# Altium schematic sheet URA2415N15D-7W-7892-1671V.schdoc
size 277 x 190 mm; Device: default297x210; Symbol: default297x210; Name: default297x210; Date: 2026.04.20; Rev: V1.1; Size: "A4"; Id: /; File: URA2415N15D-7W-7892-1671V; Sheet: /
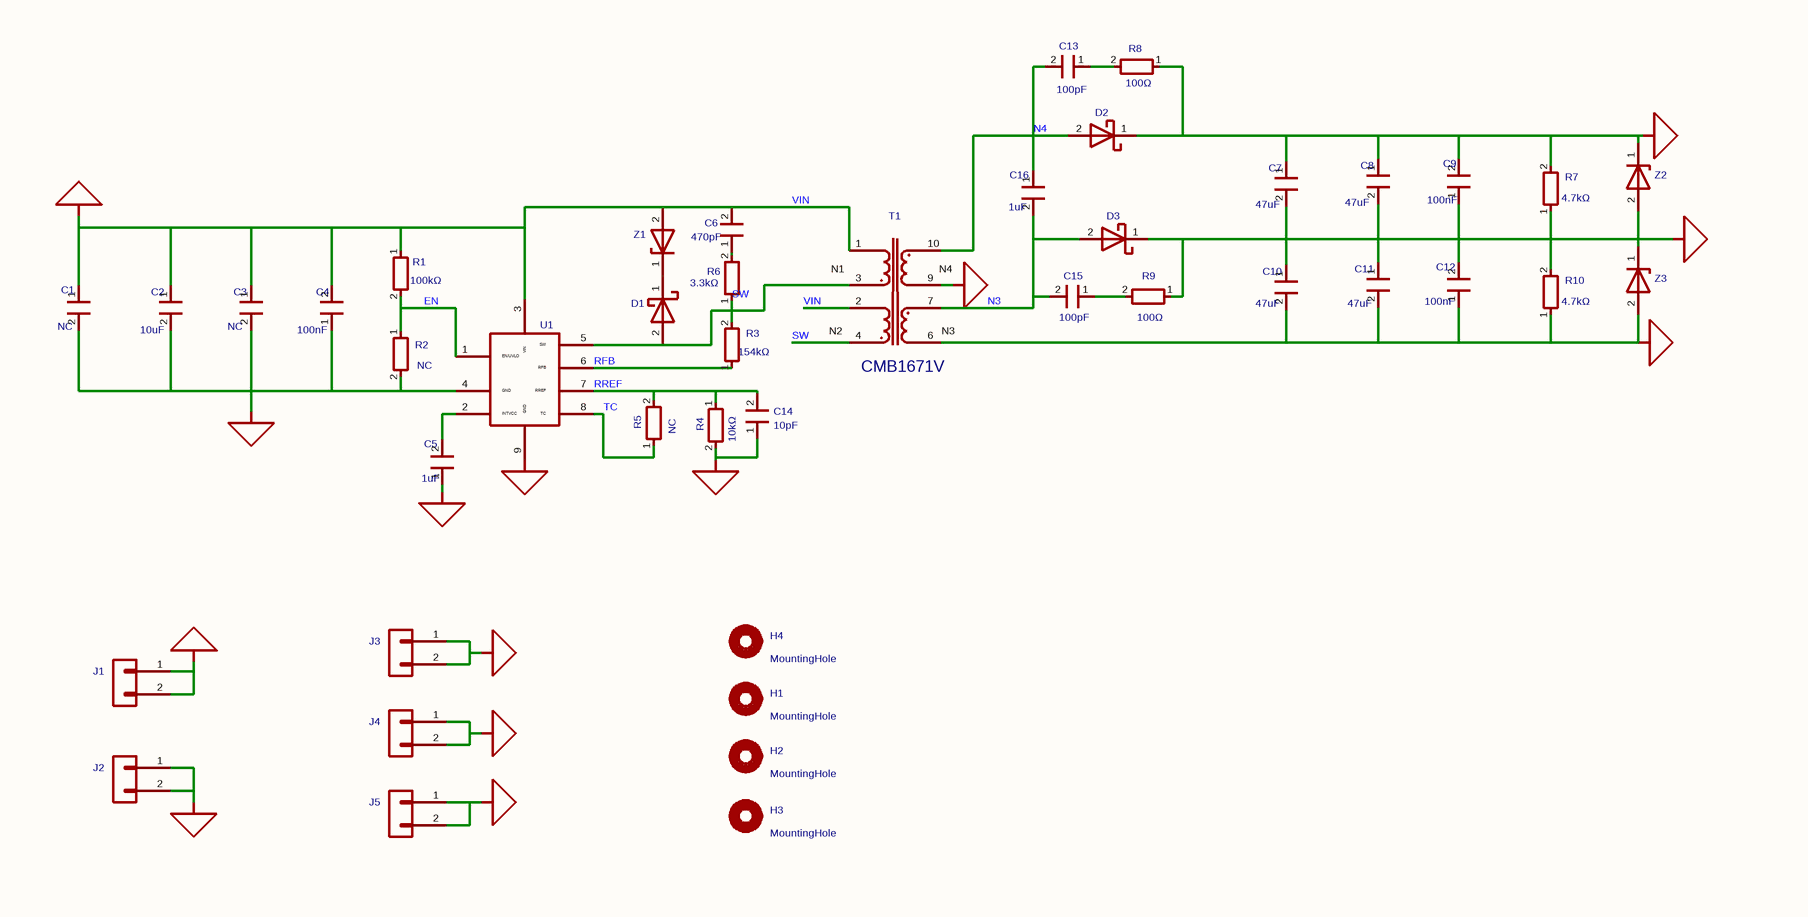
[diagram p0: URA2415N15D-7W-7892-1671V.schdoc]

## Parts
C1  value NC  [MYLibrary:C1206]  (hidden comment: MY_C)
C2  10uF  [MYLibrary:C1206]
C3  value NC  [MYLibrary:C0805]  (hidden comment: MY_C)
C4  100nF  [MYLibrary:C0603]
C5  1uF  [MYLibrary:C0603]
C6  470pF  [MYLibrary:C0603]
C7  47uF  [MYLibrary:C1206]
C8  47uF  [MYLibrary:C1206]
C9  100nF  [MYLibrary:C0603]
C10  47uF  [MYLibrary:C1206]
C11  47uF  [MYLibrary:C1206]
C12  100nF  [MYLibrary:C0603]
C13  100pF  [MYLibrary:C0603]
C14  10pF  [MYLibrary:C0603]
C15  100pF  [MYLibrary:C0603]
C16  1uF  [MYLibrary:C0805]
D1  DSS210  [Diode_SMD:D_SOD-123]  (value not drawn)
D2  SS210F  [Diode_SMD:D_SMA_Handsoldering]  (value not drawn)
D3  SS210F  [Diode_SMD:D_SMA_Handsoldering]  (value not drawn)
H1  value MountingHole  [MountingHole:MountingHole_3.2mm_M3_DIN965]  (hidden comment: Mechanical_MountingHole)
H2  value MountingHole  [MountingHole:MountingHole_3.2mm_M3_DIN965]  (hidden comment: Mechanical_MountingHole)
H3  value MountingHole  [MountingHole:MountingHole_3.2mm_M3_DIN965]  (hidden comment: Mechanical_MountingHole)
H4  value MountingHole  [MountingHole:MountingHole_3.2mm_M3_DIN965]  (hidden comment: Mechanical_MountingHole)
J1  HX PZ2.54-1x2P ZZ  [Connector_PinHeader_2.54mm:PinHeader_1x02_P2.54mm_Vertical]  (value not drawn)
J2  HX PZ2.54-1x2P ZZ  [Connector_PinHeader_2.54mm:PinHeader_1x02_P2.54mm_Vertical]  (value not drawn)
J3  HX PZ2.54-1x2P ZZ  [Connector_PinHeader_2.54mm:PinHeader_1x02_P2.54mm_Vertical]  (value not drawn)
J4  HX PZ2.54-1x2P ZZ  [Connector_PinHeader_2.54mm:PinHeader_1x02_P2.54mm_Vertical]  (value not drawn)
J5  HX PZ2.54-1x2P ZZ  [Connector_PinHeader_2.54mm:PinHeader_1x02_P2.54mm_Vertical]  (value not drawn)
R1  100kΩ  [MYLibrary:R0603]
R2  value NC  [MYLibrary:R0603]  (hidden comment: Device_R_Small)
R3  154kΩ  [MYLibrary:R0603]
R4  10kΩ  [MYLibrary:R0603]
R5  value NC  [MYLibrary:R0603]  (hidden comment: Device_R_Small)
R6  3.3kΩ  [MYLibrary:R1206]
R7  4.7kΩ  [MYLibrary:R1206]
R8  100Ω  [MYLibrary:R0603]
R9  100Ω  [MYLibrary:R0603]
R10  4.7kΩ  [MYLibrary:R1206]
T1  CMB1671V  [MYLibrary:EP13_9PIN]
U1  CMP7892  [Package_SO:SOIC-8-1EP_3.9x4.9mm_P1.27mm_EP2.41x3.3mm_ThermalVias]  (value not drawn)
Z1  1SMA4747A  [Diode_SMD:D_SMA]  (value not drawn)
Z2  Diode_BZV55C75  [Diode_SMD:D_SMA]  (value not drawn)
Z3  Diode_BZV55C75  [Diode_SMD:D_SMA]  (value not drawn)

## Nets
-VOUT2: C10.2 C11.2 C12.1 J5.1(Pin_1) J5.2(Pin_2) R10.1 T1.6 Z3.2(A)
GND1: C1.2 C2.2 C3.2 C4.1 C5.1 C14.1 J2.1(Pin_1) J2.2(Pin_2) R2.2 R4.2 U1.4(GND) U1.9(GND)
GND2: C7.2 C8.2 C9.1 C10.1 C11.1 C12.2 D3.1(K) J4.1(Pin_1) J4.2(Pin_2) R7.1 R9.1 R10.2 T1.9 Z2.2(A) Z3.1(K)
VIN: C1.1 C2.1 C3.1 C4.2 C6.2 J1.1(Pin_1) J1.2(Pin_2) R1.1 T1.1 T1.2 U1.3(VIN) Z1.2(A)
VOUT1: C7.1 C8.1 C9.2 D2.1(K) J3.1(Pin_1) J3.2(Pin_2) R7.2 R8.1 Z2.1(K)
EN: R1.2 R2.1 U1.1(EN/UVLO)
N3: C15.2 C16.2 D3.2(A) T1.7
N4: C13.2 C16.1 D2.2(A) T1.10
RFB: R3.1 U1.6(RFB)
RREF: C14.2 R4.1 R5.2 U1.7(RREF)
SW: D1.2(A) R3.2 R6.1 T1.3 T1.4 U1.5(SW)
TC: R5.1 U1.8(TC)
NetC5_2: C5.2 U1.2(INTVCC)
NetC6_1: C6.1 R6.2
NetC13_1: C13.1 R8.2
NetC15_1: C15.1 R9.2
NetD1_1: D1.1(K) Z1.1(K)

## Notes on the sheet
- (near T1) N2
- (near T1) N1
- (near T1) N4
- (near T1) N3

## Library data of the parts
C1 = MY_C: Add into BOM: no; ki_keywords: cap capacitor; ki_fp_filters: C_*; Attribute1: C11
C2 = CC1206KKX5R9BB106: 容值:10uF;精度:±10%;额定电压:50V;温度系数:X5R;; Manufacturer: YAGEO(国巨); Symbol: MY_C; Add into BOM: yes; 3D Model: e4be705b945545a48e666415e3682bd8; 3D Model Transform: 125.984,62.992,0,0,0,0,0,0,0; Tolerance: ±10%; Voltage Rating: 50V; Temperature Coefficient: X5R; ki_keywords: cap capacitor; ki_fp_filters: C_*; ModelName: C1206_L3.2-W1.6-H1.3
C3 = MY_C: 0805; Add into BOM: no; ki_keywords: cap capacitor; ki_fp_filters: C_*; Attribute1: C16
C4 C9 C12 = CC0603KRX7R9BB104: 容值:100nF;精度:±10%;额定电压:50V;温度系数:X7R;; Manufacturer: YAGEO(国巨); Symbol: MY_C; Add into BOM: yes; 3D Model: ac125912035d415993ca9572d50418b1; 3D Model Transform: 62.992,31.496,0,0,0,0,0,0,0; Tolerance: ±10%; Voltage Rating: 50V; Temperature Coefficient: X7R; ki_keywords: cap capacitor; ki_fp_filters: C_*; ModelName: C0603_L1.6-W0.8-H0.8
C5 = CC0603KRX7R9BB105: 容值:1uF;精度:±10%;额定电压:50V;温度系数:X7R;; Manufacturer: YAGEO(国巨); Symbol: MY_C; Add into BOM: yes; 3D Model: ac125912035d415993ca9572d50418b1; 3D Model Transform: 62.992,31.496,0,0,0,0,0,0,0; Tolerance: ±10%; Voltage Rating: 50V; Temperature Coefficient: X7R; ki_keywords: cap capacitor; ki_fp_filters: C_*; UniqueId: 05d417a4d81547fc; ModelName: C0603_L1.6-W0.8-H0.8
C6 = CC0603KRX7R9BB471: 容值:470pF;精度:±10%;额定电压:50V;材质(温度系数):X7R;; Manufacturer: YAGEO(国巨); Symbol: My_library_C; Add into BOM: yes; 3D Model: ac125912035d415993ca9572d50418b1; 3D Model Transform: 62.992,31.496,0,0,0,0,0,0,0; Tolerance: ±10%; Voltage Rated: 50V; Temperature Coefficient: X7R; ki_keywords: cap capacitor; ki_fp_filters: C_*; UniqueId: 2b0dbff75b6442fd; ModelName: C0603_L1.6-W0.8-H0.8
C7 = C3216X5R1E476MTJ00E: 容值:47uF;精度:±20%;额定电压:25V;温度系数:X5R;; Manufacturer: TDK; Symbol: MY_C; Add into BOM: yes; 3D Model: e4be705b945545a48e666415e3682bd8; 3D Model Transform: 125.984,62.992,0,0,0,0,0,0,0; Tolerance: ±20%; Voltage Rating: 25V; Temperature Coefficient: X5R; ki_keywords: cap capacitor; ki_fp_filters: C_*; UniqueId: 3007ca2539a35480; ModelName: C1206_L3.2-W1.6-H1.3
C8 C11 = C3216X5R1E476MTJ00E: 容值:47uF;精度:±20%;额定电压:25V;温度系数:X5R;; Manufacturer: TDK; Symbol: MY_C; Add into BOM: yes; 3D Model: e4be705b945545a48e666415e3682bd8; 3D Model Transform: 125.984,62.992,0,0,0,0,0,0,0; Tolerance: ±20%; Voltage Rating: 25V; Temperature Coefficient: X5R; ki_keywords: cap capacitor; ki_fp_filters: C_*; ModelName: C1206_L3.2-W1.6-H1.3
C10 = C3216X5R1E476MTJ00E: 容值:47uF;精度:±20%;额定电压:25V;温度系数:X5R;; Manufacturer: TDK; Symbol: MY_C; Add into BOM: yes; 3D Model: e4be705b945545a48e666415e3682bd8; 3D Model Transform: 125.984,62.992,0,0,0,0,0,0,0; Tolerance: ±20%; Voltage Rating: 25V; Temperature Coefficient: X5R; ki_keywords: cap capacitor; ki_fp_filters: C_*; UniqueId: c1764753ee6525b4; ModelName: C1206_L3.2-W1.6-H1.3
C13 = CC0603JRNPO9BN101: 容值:100pF;精度:±5%;额定电压:50V;温度系数:NP0;; Manufacturer: YAGEO(国巨); Symbol: My_library_C; Add into BOM: yes; 3D Model: ac125912035d415993ca9572d50418b1; 3D Model Transform: 62.992,31.496,0,0,0,0,0,0,0; Tolerance: ±5%; Voltage Rating: 50V; Temperature Coefficient: NP0; ki_keywords: cap capacitor; ki_fp_filters: C_*; UniqueId: 8d11a04c32f33369; ModelName: C0603_L1.6-W0.8-H0.8
C14 = CC0603JRNPO9BN100: 容值:10pF;精度:±5%;额定电压:50V;温度系数:NP0;; Manufacturer: YAGEO(国巨); Symbol: My_library_C; Add into BOM: yes; 3D Model: ac125912035d415993ca9572d50418b1; 3D Model Transform: 62.992,31.496,0,0,0,0,0,0,0; Tolerance: ±5%; Voltage Rating: 50V; Temperature Coefficient: NP0; ki_keywords: cap capacitor; ki_fp_filters: C_*; UniqueId: c9f451b8b2c5f180; ModelName: C0603_L1.6-W0.8-H0.8
C15 = CC0603JRNPO9BN101: 容值:100pF;精度:±5%;额定电压:50V;温度系数:NP0;; Manufacturer: YAGEO(国巨); Symbol: My_library_C; Add into BOM: yes; 3D Model: ac125912035d415993ca9572d50418b1; 3D Model Transform: 62.992,31.496,0,0,0,0,0,0,0; Tolerance: ±5%; Voltage Rating: 50V; Temperature Coefficient: NP0; ki_keywords: cap capacitor; ki_fp_filters: C_*; UniqueId: 4a0fa0f8d5a09ecc; ModelName: C0603_L1.6-W0.8-H0.8
C16 = CL21B105KBFNNNE: 容值:1uF;精度:±10%;额定电压:50V;温度系数:X7R;; Manufacturer: SAMSUNG(三星); Symbol: My_library_C; Add into BOM: yes; 3D Model: ac125912035d415993ca9572d50418b1; 3D Model Transform: 78.74,51.181,0,0,0,0,0,0.0005,0; Tolerance: ±10%; Voltage Rating: 50V; Temperature Coefficient: X7R; ki_keywords: cap capacitor; ki_fp_filters: C_*; UniqueId: 6992a3033003bbbd; ModelName: C0805_L2.0-W1.3-H1.3
D1 = DSS210: 二极管配置:独立式;正向压降(Vf):850mV@2A;直流反向耐压(Vr):100V;整流电流:2A;; Manufacturer: CJ(江苏长电/长晶); Symbol: My library_DSS210; Add into BOM: yes; 3D Model: 125b22121bda4d3999c0a2016797619b; 3D Model Transform: 145.669,70.866,0,0,0,0,0,0,0; Diode Configuration: 独立式; Voltage - DC Reverse(Vr): 100V; Current - Rectified: 2A; Reverse Leakage Current (Ir): 100uA@100V; Operating Junction Temperature Range: -55℃~+150℃; Non-Repetitive Peak Forward Surge Current: 40A; ki_keywords: diode; ki_fp_filters: TO-???* *_Diode_* *SingleDiode* D_*; UniqueId: de80be6c74b1ca94; ModelName: SOD-123_L2.8-W1.8-H1.4-LS3.7
D2 = SS210F_C408387: 二极管配置:独立式;正向压降(Vf):850mV@2A;直流反向耐压(Vr):100V;整流电流:2A;; Manufacturer: MDD(辰达半导体); Symbol: My library_DSS210; Add into BOM: yes; 3D Model: b8c4b3388b3d4c198b22b876116f592b; 3D Model Transform: 183.0705,102.362,0,0,0,0,0,0,0; Diode Configuration: 独立式; Voltage - DC Reverse(Vr): 100V; Current - Rectified: 2A; Reverse Leakage Current (Ir): 300uA@100V; Operating Junction Temperature Range: -55℃~+150℃; Value: DSS210; ki_keywords: diode; ki_fp_filters: TO-???* *_Diode_* *SingleDiode* D_*; UniqueId: gge1; ModelName: SMAF_L3.5-W2.6-LS4.7-RD-1
D3 = SS210F_C408387: 二极管配置:独立式;正向压降(Vf):850mV@2A;直流反向耐压(Vr):100V;整流电流:2A;; Manufacturer: MDD(辰达半导体); Symbol: My library_DSS210; Add into BOM: yes; 3D Model: b8c4b3388b3d4c198b22b876116f592b; 3D Model Transform: 183.0705,102.362,0,0,0,0,0,0,0; Diode Configuration: 独立式; Voltage - DC Reverse(Vr): 100V; Current - Rectified: 2A; Reverse Leakage Current (Ir): 300uA@100V; Operating Junction Temperature Range: -55℃~+150℃; Value: DSS210; ki_keywords: diode; ki_fp_filters: TO-???* *_Diode_* *SingleDiode* D_*; UniqueId: ce0e29427420bb9a; ModelName: SMAF_L3.5-W2.6-LS4.7-RD-1
H1-H4 = Mechanical_MountingHole: ki_fp_filters: MountingHole*; Attribute1: H1; AddInBom: yes
J1-J5 = HX PZ2.54-1x2P ZZ: 插针结构:1x2P;间距:2.54mm;行距:-;圆针/方针:方针;安装方式:直插;排数:单排;总PIN位数:2P;额定电流:3A;额定电压:1kV;配合针长度:6mm;塑高:2.5mm;端接针长度:3mm;触头材质:黄铜;触头镀层:金;工作温度:-40℃~+105℃;颜色:黑色;; Manufacturer: hanxia(韩下); Symbol: Connector_Generic_Conn_01x02; Add into BOM: yes; 3D Model: c7a9f3c3e6e34627af2bf939e464cb35; 3D Model Transform: 200,100,0,0,0,0,0,0,-118.11; Pin Structure: 1x2P; Pitch: 2.54mm; Circluar Pins/Square Pins: 方针; Current Rating: 3A; Voltage Rating (Max): 1kV; ki_keywords: connector; ki_fp_filters: Connector*:*_1x??_*; ModelName: HDR-TH_2P-P2.54-M-LI-1X2P
R1 = RC0603FR-07100KL: 电阻类型:厚膜电阻;阻值:100kΩ;精度:±1%;功率:100mW;最大工作电压:75V;温度系数:±100ppm/℃;; Manufacturer: YAGEO(国巨); Symbol: Device_R_Small; Add into BOM: yes; 3D Model: fc143cca1e79419f9cd78b61e9279f08; 3D Model Transform: 31.8897,63.7794,0,90,0,0,0,0,0; Tolerance: ±1%; Power(Watts): 100mW; Overload Voltage (Max): 75V; ki_keywords: R resistor; ki_fp_filters: R_*; ModelName: R0603
R2 R5 = Device_R_Small: Resistor, small symbol; Add into BOM: no; ki_keywords: R resistor; ki_fp_filters: R_*; Attribute1: R8
R3 = RC0603FR-07154KL: 电阻类型:厚膜电阻;阻值:154kΩ;精度:±1%;功率:100mW;最大工作电压:75V;温度系数:±100ppm/℃;; Manufacturer: YAGEO(国巨); Symbol: Device_R_Small; Add into BOM: yes; 3D Model: fc143cca1e79419f9cd78b61e9279f08; 3D Model Transform: 31.8897,63.7794,0,90,0,0,0,0,0; Tolerance: ±1%; Power(Watts): 100mW; Overload Voltage (Max): 75V; ki_keywords: R resistor; ki_fp_filters: R_*; UniqueId: 6e26aea592918673; ModelName: R0603
R4 = RC0603FR-0710KL: 电阻类型:厚膜电阻;阻值:10kΩ;精度:±1%;功率:100mW;最大工作电压:75V;温度系数:±100ppm/℃;; Manufacturer: YAGEO(国巨); Symbol: Device_R_Small; Add into BOM: yes; 3D Model: fc143cca1e79419f9cd78b61e9279f08; 3D Model Transform: 31.8897,63.7794,0,90,0,0,0,0,0; Tolerance: ±1%; Power(Watts): 100mW; Overload Voltage (Max): 75V; ki_keywords: R resistor; ki_fp_filters: R_*; ModelName: R0603
R6 = RC1206FR-073K3L: 电阻类型:厚膜电阻;阻值:3.3kΩ;精度:±1%;功率:250mW;工作电压:200V;温度系数:±100ppm/℃;; Manufacturer: YAGEO(国巨); Symbol: Device_R_Small; Add into BOM: yes; 3D Model: 89a1f13db2384da588040e0b3c55bf66; 3D Model Transform: 125.984,62.992,0,0,0,0,0,0,0; Tolerance: ±1%; Power(Watts): 250mW; Voltage-Supply(Max): 200V; ki_keywords: R resistor; ki_fp_filters: R_*; UniqueId: c9a24d22ca7022dc; ModelName: R1206_L3.2-W1.6-H0.6
R7 = AC1206FR-074K7L: 电阻类型:厚膜电阻;阻值:4.7kΩ;精度:±1%;功率:250mW;最大工作电压:200V;温度系数:±100ppm/℃;; Manufacturer: YAGEO(国巨); Symbol: Device_R_Small; Add into BOM: yes; 3D Model: 89a1f13db2384da588040e0b3c55bf66; 3D Model Transform: 125.984,62.992,0,0,0,0,0,0,0; Tolerance: ±1%; Power(Watts): 250mW; Overload Voltage (Max): 200V; ki_keywords: R resistor; ki_fp_filters: R_*; UniqueId: 01f5c70ff2630ee7; ModelName: R1206_L3.2-W1.6-H0.6
R8 = RC0603FR-07100RL: 电阻类型:厚膜电阻;阻值:100Ω;精度:±1%;功率:100mW;最大工作电压:75V;温度系数:±100ppm/℃;; Manufacturer: YAGEO(国巨); Symbol: Device_R_Small; Add into BOM: yes; 3D Model: fc143cca1e79419f9cd78b61e9279f08; 3D Model Transform: 31.8897,63.7794,0,90,0,0,0,0,0; Tolerance: ±1%; Power(Watts): 100mW; Overload Voltage (Max): 75V; ki_keywords: R resistor; ki_fp_filters: R_*; UniqueId: f0665cc51e401020; ModelName: R0603
R9 = RC0603FR-07100RL: 电阻类型:厚膜电阻;阻值:100Ω;精度:±1%;功率:100mW;最大工作电压:75V;温度系数:±100ppm/℃;; Manufacturer: YAGEO(国巨); Symbol: Device_R_Small; Add into BOM: yes; 3D Model: fc143cca1e79419f9cd78b61e9279f08; 3D Model Transform: 31.8897,63.7794,0,90,0,0,0,0,0; Tolerance: ±1%; Power(Watts): 100mW; Overload Voltage (Max): 75V; ki_keywords: R resistor; ki_fp_filters: R_*; UniqueId: 7a9d276dcc23a651; ModelName: R0603
R10 = AC1206FR-074K7L: 电阻类型:厚膜电阻;阻值:4.7kΩ;精度:±1%;功率:250mW;最大工作电压:200V;温度系数:±100ppm/℃;; Manufacturer: YAGEO(国巨); Symbol: Device_R_Small; Add into BOM: yes; 3D Model: 89a1f13db2384da588040e0b3c55bf66; 3D Model Transform: 125.984,62.992,0,0,0,0,0,0,0; Tolerance: ±1%; Power(Watts): 250mW; Overload Voltage (Max): 200V; ki_keywords: R resistor; ki_fp_filters: R_*; UniqueId: 7663007c1f2bc029; ModelName: R1206_L3.2-W1.6-H0.6
T1 = CMB1671V: Manufacturer: coileasy(线易); Add into BOM: yes; 3D Model: 68a99e8f81ae47cc9e54feb7acf58219; 3D Model Transform: 707.8726,531.495,0,0,0,0,0,0,0; Origin Footprint: MYLibrary:EP13; UniqueId: cf2c480e5945250c; ModelName: XFMR-SMD_CMB1671V
U1 = CMP7892: Manufacturer: coileasy(线易); Add into BOM: yes; 3D Model: f43fc10339aa42ce991094e4756959b9; 3D Model Transform: 192.913,236.22,0,0,0,0,0,0,0; UniqueId: 48a4a086d8c42a18; ModelName: ESOP-8_L4.9-W3.9-P1.27-LS6.0-BL-EP3.3
Z1 = 1SMA4747A: 二极管配置:独立式;稳压值(标称值):20V;稳压值(范围):19V~21V;耗散功率(Pd):1W;; Manufacturer: LGE(鲁光); Symbol: Diode_BZV55C75; Add into BOM: yes; 3D Model: e3551acb3c5a4975a5e9d36087fe1fa2; 3D Model Transform: 185.039,102.362,0,0,0,0,0,0,0; Diode Configuration: 独立式; Zener Voltage(Nom): 20V; Reverse Leakage Current (Ir): 5uA@1.0V; Pd - Power Dissipation: 1W; Impedance(Zzt): 22Ω; Operating Junction Temperature Range: -55℃~+150℃; ki_keywords: zener diode; ki_fp_filters: D*MiniMELF*; Origin Footprint: Diode_SMD:D_MiniMELF; UniqueId: d022797895385730; ModelName: SMA_L4.3-W2.6-LS5.2-RD
Z2 = Diode_BZV55C75: Value: ~; Add into BOM: no; ki_keywords: zener diode; ki_fp_filters: D*MiniMELF*; Origin Footprint: Diode_SMD:D_MiniMELF; UniqueId: 2477e26b20e1c3a5; Attribute1: Z2
Z3 = Diode_BZV55C75: Value: ~; Add into BOM: no; ki_keywords: zener diode; ki_fp_filters: D*MiniMELF*; Origin Footprint: Diode_SMD:D_MiniMELF; UniqueId: c4edca6e17623a03; Attribute1: Z2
